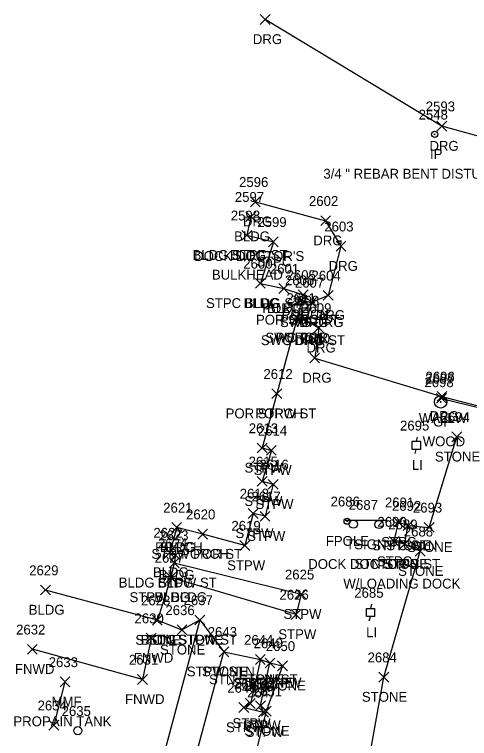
# Model space of a CAD drawing. Extents: x 1443071 to 1445292, y 614024 to 622563.
# Drawn here: x 1443947.5 to 1444039.9, y 620180.3 to 620327.3 of the extents above; entities that cross this region are included whole.
import ezdxf

# ---------------------------------------------------------------- set-up
doc = ezdxf.new("R2010")
doc.units = 0
for name, color, linetype in [('L_A', 7, 'Continuous'), ('L_C', 7, 'Continuous'), ('L_I', 7, 'Continuous'), ('L_TIC', 7, 'Continuous'), ('LASF', 7, 'Continuous'), ('LBC', 7, 'Continuous'), ('LBF', 7, 'Continuous'), ('LDEFAULT', 7, 'Continuous'), ('LFNC', 7, 'Continuous'), ('LFP', 7, 'Continuous'), ('LW', 7, 'Continuous'), ('M_A', 7, 'Continuous'), ('M_C', 7, 'Continuous'), ('M_I', 7, 'Continuous'), ('MPIR', 7, 'Continuous'), ('R_A', 7, 'Continuous'), ('R_C', 7, 'Continuous'), ('R_I', 7, 'Continuous'), ('R_TIC', 7, 'Continuous'), ('RDG', 7, 'Continuous'), ('RGP', 7, 'Continuous'), ('RSW', 7, 'Continuous'), ('S_A', 7, 'Continuous'), ('S_C', 7, 'Continuous'), ('S_I', 7, 'Continuous'), ('SSGN', 7, 'Continuous'), ('U_A', 7, 'Continuous'), ('U_I', 7, 'Continuous'), ('ULP', 7, 'Continuous'), ('UUMH', 7, 'Continuous')]:
    doc.layers.add(name, color=color, linetype=linetype)

msp = doc.modelspace()

# ---------------------------------------------------------------- linework, layer by layer
at = {"layer": 'L_TIC'}
for points in [[(1443994.5, 620285.22), (1443996.5, 620287.22)], [(1443996.5, 620285.22), (1443994.5, 620287.22)], [(1443993.68, 620281.44), (1443995.68, 620283.44)], [(1443995.68, 620281.44), (1443993.68, 620283.44)], [(1443993.68, 620281.44), (1443995.68, 620283.44)], [(1443995.68, 620281.44), (1443993.68, 620283.44)], [(1443999.07, 620280.11), (1444001.07, 620282.11)], [(1444001.07, 620280.11), (1443999.07, 620282.11)], [(1443996.43, 620271.67), (1443998.43, 620273.67)], [(1443998.43, 620271.67), (1443996.43, 620273.67)], [(1443996.43, 620271.67), (1443998.43, 620273.67)], [(1443998.43, 620271.67), (1443996.43, 620273.67)], [(1444001.18, 620270.64), (1444003.18, 620272.64)], [(1444003.18, 620270.64), (1444001.18, 620272.64)], [(1444001.18, 620270.64), (1444003.18, 620272.64)], [(1444003.18, 620270.64), (1444001.18, 620272.64)], [(1444005.13, 620269.35), (1444007.13, 620271.35)], [(1444007.13, 620269.35), (1444005.13, 620271.35)], [(1444004.85, 620268.3), (1444006.85, 620270.3)], [(1444006.85, 620268.3), (1444004.85, 620270.3)], [(1444003.9, 620264.67), (1444005.9, 620266.67)], [(1444005.9, 620264.67), (1444003.9, 620266.67)], [(1443999.79, 620249.28), (1444001.79, 620251.28)], [(1444001.79, 620249.28), (1443999.79, 620251.28)], [(1443999.79, 620249.28), (1444001.79, 620251.28)], [(1444001.79, 620249.28), (1443999.79, 620251.28)], [(1444033.21, 620248.34), (1444035.21, 620250.34)], [(1444035.21, 620248.34), (1444033.21, 620250.34)], [(1444036.34, 620240.52), (1444038.34, 620242.52)], [(1444038.34, 620240.52), (1444036.34, 620242.52)], [(1443996.81, 620238.26), (1443998.81, 620240.26)], [(1443998.81, 620238.26), (1443996.81, 620240.26)], [(1443998.66, 620237.78), (1444000.66, 620239.78)], [(1444000.66, 620237.78), (1443998.66, 620239.78)], [(1443996.78, 620231.5), (1443998.78, 620233.5)], [(1443998.78, 620231.5), (1443996.78, 620233.5)], [(1443999.04, 620230.89), (1444001.04, 620232.89)], [(1444001.04, 620230.89), (1443999.04, 620232.89)], [(1443994.97, 620224.98), (1443996.97, 620226.98)], [(1443996.97, 620224.98), (1443994.97, 620226.98)], [(1443997.37, 620224.4), (1443999.37, 620226.4)], [(1443999.37, 620224.4), (1443997.37, 620226.4)], [(1443979.43, 620222.14), (1443981.43, 620224.14)], [(1443981.43, 620222.14), (1443979.43, 620224.14)], [(1443979.43, 620222.14), (1443981.43, 620224.14)], [(1443981.43, 620222.14), (1443979.43, 620224.14)], [(1444024.47, 620223.2), (1444026.47, 620225.2)], [(1444026.47, 620223.2), (1444024.47, 620225.2)], [(1444026.45, 620222.51), (1444028.45, 620224.51)], [(1444028.45, 620222.51), (1444026.45, 620224.51)], [(1444026.45, 620222.51), (1444028.45, 620224.51)], [(1444028.45, 620222.51), (1444026.45, 620224.51)], [(1444030.72, 620222.15), (1444032.72, 620224.15)], [(1444032.72, 620222.15), (1444030.72, 620224.15)], [(1443984.72, 620220.77), (1443986.72, 620222.77)], [(1443986.72, 620220.77), (1443984.72, 620222.77)], [(1443984.72, 620220.77), (1443986.72, 620222.77)], [(1443986.72, 620220.77), (1443984.72, 620222.77)], [(1444023.61, 620219.27), (1444025.61, 620221.27)], [(1444025.61, 620219.27), (1444023.61, 620221.27)], [(1443993.28, 620218.46), (1443995.28, 620220.46)], [(1443995.28, 620218.46), (1443993.28, 620220.46)], [(1444025.72, 620218.74), (1444027.72, 620220.74)], [(1444027.72, 620218.74), (1444025.72, 620220.74)], [(1444025.72, 620218.74), (1444027.72, 620220.74)], [(1444027.72, 620218.74), (1444025.72, 620220.74)], [(1443978.01, 620217.04), (1443980.01, 620219.04)], [(1443980.01, 620217.04), (1443978.01, 620219.04)], [(1443979.19, 620216.52), (1443981.19, 620218.52)], [(1443981.19, 620216.52), (1443979.19, 620218.52)], [(1444028.87, 620217.3), (1444030.87, 620219.3)], [(1444030.87, 620217.3), (1444028.87, 620219.3)], [(1443978.95, 620214.94), (1443980.95, 620216.94)], [(1443980.95, 620214.94), (1443978.95, 620216.94)], [(1443978.95, 620214.94), (1443980.95, 620216.94)], [(1443980.95, 620214.94), (1443978.95, 620216.94)], [(1443978.26, 620211.98), (1443980.26, 620213.98)], [(1443980.26, 620211.98), (1443978.26, 620213.98)], [(1443978.26, 620211.98), (1443980.26, 620213.98)], [(1443980.26, 620211.98), (1443978.26, 620213.98)], [(1443952.79, 620209.43), (1443954.79, 620211.43)], [(1443954.79, 620209.43), (1443952.79, 620211.43)], [(1444004.73, 620208.57), (1444006.73, 620210.57)], [(1444006.73, 620208.57), (1444004.73, 620210.57)], [(1444003.68, 620204.47), (1444005.68, 620206.47)], [(1444005.68, 620204.47), (1444003.68, 620206.47)], [(1443975.5, 620203.31), (1443977.5, 620205.31)], [(1443977.5, 620203.31), (1443975.5, 620205.31)], [(1443975.5, 620203.31), (1443977.5, 620205.31)], [(1443977.5, 620203.31), (1443975.5, 620205.31)], [(1443984.13, 620203.36), (1443986.13, 620205.36)], [(1443986.13, 620203.36), (1443984.13, 620205.36)], [(1443984.13, 620203.36), (1443986.13, 620205.36)], [(1443986.13, 620203.36), (1443984.13, 620205.36)], [(1443980.5, 620201.34), (1443982.5, 620203.34)], [(1443982.5, 620201.34), (1443980.5, 620203.34)], [(1443974.25, 620199.68), (1443976.25, 620201.68)], [(1443976.25, 620199.68), (1443974.25, 620201.68)], [(1443950.11, 620197.4), (1443952.11, 620199.4)], [(1443952.11, 620197.4), (1443950.11, 620199.4)], [(1443989.03, 620196.9), (1443991.03, 620198.9)], [(1443991.03, 620196.9), (1443989.03, 620198.9)], [(1443989.03, 620196.9), (1443991.03, 620198.9)], [(1443991.03, 620196.9), (1443989.03, 620198.9)], [(1443996.43, 620195.31), (1443998.43, 620197.31)], [(1443998.43, 620195.31), (1443996.43, 620197.31)], [(1443996.43, 620195.31), (1443998.43, 620197.31)], [(1443998.43, 620195.31), (1443996.43, 620197.31)], [(1443998.37, 620194.62), (1444000.37, 620196.62)], [(1444000.37, 620194.62), (1443998.37, 620196.62)], [(1443998.37, 620194.62), (1444000.37, 620196.62)], [(1444000.37, 620194.62), (1443998.37, 620196.62)], [(1444000.92, 620194.04), (1444002.92, 620196.04)], [(1444002.92, 620194.04), (1444000.92, 620196.04)], [(1443972.47, 620191.28), (1443974.47, 620193.28)], [(1443974.47, 620191.28), (1443972.47, 620193.28)], [(1444021.51, 620191.75), (1444023.51, 620193.75)], [(1444023.51, 620191.75), (1444021.51, 620193.75)], [(1443956.73, 620190.78), (1443958.73, 620192.78)], [(1443958.73, 620190.78), (1443956.73, 620192.78)], [(1443993.06, 620185.58), (1443995.06, 620187.58)], [(1443995.06, 620185.58), (1443993.06, 620187.58)], [(1443994.39, 620186.41), (1443996.39, 620188.41)], [(1443996.39, 620186.41), (1443994.39, 620188.41)], [(1443996.45, 620185.96), (1443998.45, 620187.96)], [(1443998.45, 620185.96), (1443996.45, 620187.96)], [(1443997.05, 620184.62), (1443999.05, 620186.62)], [(1443999.05, 620184.62), (1443997.05, 620186.62)], [(1443997.63, 620184.84), (1443999.63, 620186.84)], [(1443999.63, 620184.84), (1443997.63, 620186.84)], [(1443954.48, 620181.99), (1443956.48, 620183.99)], [(1443956.48, 620181.99), (1443954.48, 620183.99)]]:
    msp.add_lwpolyline(points, dxfattribs=at)
at = {"layer": 'LASF'}
msp.add_lwpolyline([(1443976.5, 620204.31), (1443981.5, 620202.34), (1443985.13, 620204.36), (1443990.03, 620197.9), (1443997.43, 620196.31), (1443999.37, 620195.62), (1444001.92, 620195.04), (1443998.63, 620185.84), (1443991.95, 620159.42), (1443988.85, 620147.15), (1443986.19, 620136.52), (1443986.57, 620129.75), (1444004.87, 620124.73), (1444012.6, 620137.5), (1444022.51, 620192.75), (1444029.87, 620218.3), (1444026.72, 620219.74), (1444027.45, 620223.51), (1444031.72, 620223.15), (1444037.34, 620241.52)], dxfattribs=at)
at = {"layer": 'LBC'}
for points in [[(1443995.5, 620286.22), (1443994.68, 620282.44)], [(1443997.43, 620272.67), (1444002.18, 620271.64)], [(1443980.43, 620223.14), (1443979.01, 620218.04), (1443980.19, 620217.52), (1443979.95, 620215.94), (1443979.26, 620212.98), (1443976.5, 620204.31), (1443953.79, 620210.43)]]:
    msp.add_lwpolyline(points, dxfattribs=at)
at = {"layer": 'LBF'}
for points in [[(1443994.68, 620282.44), (1444000.07, 620281.11), (1443997.43, 620272.67)], [(1444002.18, 620271.64), (1444006.13, 620270.35), (1444005.85, 620269.3), (1444004.9, 620265.67), (1444000.79, 620250.28)], [(1444000.79, 620250.28), (1443997.81, 620239.26), (1443999.66, 620238.78), (1443997.78, 620232.5), (1444000.04, 620231.89), (1443998.37, 620225.4), (1443995.97, 620225.98), (1443994.28, 620219.46), (1443985.72, 620221.77)], [(1444026.72, 620219.74), (1444024.61, 620220.27), (1444025.47, 620224.2), (1444027.45, 620223.51)], [(1443985.72, 620221.77), (1443980.43, 620223.14)], [(1443979.95, 620215.94), (1444005.73, 620209.57), (1444004.68, 620205.47), (1443979.26, 620212.98)], [(1443985.13, 620204.36), (1443975.11, 620166.96), (1443990.62, 620162.19), (1443992.36, 620167.94), (1443985.21, 620169.98), (1443983.8, 620174.72), (1443990.03, 620197.9)], [(1443997.43, 620196.31), (1443995.39, 620187.41), (1443994.06, 620186.58), (1443998.05, 620185.62), (1443997.45, 620186.96), (1443999.37, 620195.62)]]:
    msp.add_lwpolyline(points, dxfattribs=at)
at = {"layer": 'LDEFAULT'}
msp.add_lwpolyline([(1443957.73, 620191.78), (1443955.48, 620182.99)], dxfattribs=at)
at = {"layer": 'LFNC'}
msp.add_lwpolyline([(1443975.25, 620200.68), (1443973.47, 620192.28), (1443951.11, 620198.4)], dxfattribs=at)
at = {"layer": 'LFP'}
for radius in [0.625, 0.0833]:
    msp.add_circle((1444015.05, 620224.39), radius, dxfattribs=at)
at = {"layer": 'LW'}
msp.add_lwpolyline([(1444034.21, 620249.34), (1444044.78, 620246.72), (1444050.66, 620270.57), (1444050.35, 620270.75)], dxfattribs=at)
at = {"layer": 'MPIR'}
for radius in [0.625, 0.0833]:
    msp.add_circle((1444032.83, 620302.93), radius, dxfattribs=at)
at = {"layer": 'R_TIC'}
for points in [[(1443997.41, 620325.25), (1443999.41, 620327.25)], [(1443999.41, 620325.25), (1443997.41, 620327.25)], [(1444033.28, 620303.59), (1444035.28, 620305.59)], [(1444035.28, 620303.59), (1444033.28, 620305.59)], [(1443995.41, 620288.24), (1443997.41, 620290.24)], [(1443997.41, 620288.24), (1443995.41, 620290.24)], [(1444009.68, 620284.39), (1444011.68, 620286.39)], [(1444011.68, 620284.39), (1444009.68, 620286.39)], [(1444012.79, 620279.22), (1444014.79, 620281.22)], [(1444014.79, 620279.22), (1444012.79, 620281.22)], [(1444010.2, 620269.24), (1444012.2, 620271.24)], [(1444012.2, 620269.24), (1444010.2, 620271.24)], [(1444004.85, 620268.3), (1444006.85, 620270.3)], [(1444006.85, 620268.3), (1444004.85, 620270.3)], [(1444006.82, 620267.81), (1444008.82, 620269.81)], [(1444008.82, 620267.81), (1444006.82, 620269.81)], [(1444006.82, 620267.81), (1444008.82, 620269.81)], [(1444008.82, 620267.81), (1444006.82, 620269.81)], [(1444003.9, 620264.67), (1444005.9, 620266.67)], [(1444005.9, 620264.67), (1444003.9, 620266.67)], [(1444005.82, 620264.14), (1444007.82, 620266.14)], [(1444007.82, 620264.14), (1444005.82, 620266.14)], [(1444005.82, 620264.14), (1444007.82, 620266.14)], [(1444007.82, 620264.14), (1444005.82, 620266.14)], [(1444008.31, 620262.64), (1444010.31, 620264.64)], [(1444010.31, 620262.64), (1444008.31, 620264.64)], [(1444007.46, 620256.52), (1444009.46, 620258.52)], [(1444009.46, 620256.52), (1444007.46, 620258.52)], [(1444033.32, 620248.74), (1444035.32, 620250.74)], [(1444035.32, 620248.74), (1444033.32, 620250.74)]]:
    msp.add_lwpolyline(points, dxfattribs=at)
at = {"layer": 'RDG'}
for points in [[(1444067.43, 620324.85), (1444069.07, 620313.31), (1444066.3, 620300.78), (1444063.63, 620298.79), (1444051.48, 620299.88), (1444034.28, 620304.59), (1443998.41, 620326.25)], [(1443996.41, 620289.24), (1444010.68, 620285.39), (1444013.79, 620280.22), (1444011.2, 620270.24), (1444007.82, 620268.81)], [(1444006.82, 620265.14), (1444009.31, 620263.64), (1444008.46, 620257.52), (1444034.32, 620249.74), (1444044.54, 620247.09), (1444050.35, 620270.75), (1444052.51, 620273.19), (1444063.33, 620265.17), (1444066.93, 620257.79), (1444075.53, 620245.02)]]:
    msp.add_lwpolyline(points, dxfattribs=at)
at = {"layer": 'RGP'}
msp.add_line((1444034.05, 620248.61), (1444034.05, 620248.61), dxfattribs=at)
for radius in [1.25, 0.0833]:
    msp.add_circle((1444034.05, 620248.61), radius, dxfattribs=at)
at = {"layer": 'RSW'}
msp.add_lwpolyline([(1444005.85, 620269.3), (1444007.82, 620268.81), (1444006.82, 620265.14), (1444004.9, 620265.67)], dxfattribs=at)
at = {"layer": 'SSGN'}
for p, q in [((1444014.66, 620224.63), (1444023.26, 620224.63)), ((1444018.68, 620223.73), (1444018.68, 620223.73))]:
    msp.add_line(p, q, dxfattribs=at)
for centre in [(1444016.32, 620223.8), (1444021.54, 620223.73)]:
    msp.add_circle(centre, 0.833, dxfattribs=at)
at = {"layer": 'ULP'}
for p, q in [((1444029.26, 620241.48), (1444029.1, 620240.65)), ((1444028.26, 620238.98), (1444028.26, 620240.65)), ((1444028.26, 620240.65), (1444029.93, 620240.65)), ((1444029.93, 620240.65), (1444029.93, 620238.98)), ((1444029.93, 620238.98), (1444028.26, 620238.98)), ((1444028.85, 620238.15), (1444029.1, 620238.98)), ((1444029.1, 620239.81), (1444029.1, 620239.81)), ((1444018.97, 620205.03), (1444018.97, 620206.7)), ((1444018.97, 620206.7), (1444020.64, 620206.7)), ((1444019.97, 620207.53), (1444019.8, 620206.7)), ((1444020.64, 620206.7), (1444020.64, 620205.03)), ((1444020.64, 620205.03), (1444018.97, 620205.03)), ((1444019.55, 620204.2), (1444019.8, 620205.03)), ((1444019.8, 620205.86), (1444019.8, 620205.86))]:
    msp.add_line(p, q, dxfattribs=at)
at = {"layer": 'UUMH'}
for p, q in [((1443960.36, 620181.87), (1443960.36, 620181.87)), ((1443961.2, 620181.87), (1443961.2, 620181.87))]:
    msp.add_line(p, q, dxfattribs=at)
msp.add_circle((1443960.36, 620181.87), 0.833, dxfattribs=at)

# ---------------------------------------------------------------- texts
at = {"layer": 'L_A'}
for s, p in [('BLDG', (1443992.09, 620281.22)), ('BLDG STPC ST', (1443983.65, 620277.44)), ('BLDG', (1443991.27, 620277.44)), ('STPC', (1443996.59, 620276.11)), ('STPC BLDG ST', (1443986.39, 620267.67)), ('BLDG', (1443994.02, 620267.67)), ('PORCH', (1443997.81, 620266.64)), ('BLDG', (1443998.77, 620266.64)), ('PORCH', (1444001.75, 620265.35)), ('PORCH', (1444001.47, 620264.3)), ('PORCH', (1444000.52, 620260.67)), ('POR STPW ST', (1443990.37, 620245.28)), ('PORCH', (1443996.41, 620245.28)), ('WALLW', (1444029.62, 620244.34)), ('STONE', (1444032.88, 620236.52)), ('STPW', (1443994.21, 620234.26)), ('STPW', (1443996.05, 620233.78)), ('STPW', (1443994.18, 620227.5)), ('STPW', (1443996.43, 620226.89)), ('STPW', (1443992.37, 620220.98)), ('STPW', (1443994.76, 620220.4)), ('FPOLE', (1444010.72, 620219.39)), ('STPC', (1444021.98, 620219.2)), ('PORCH', (1443976.05, 620218.14)), ('BLDG', (1443977.02, 620218.14)), ('STPC STN', (1444020.15, 620218.51)), ('STONE', (1444023, 620218.51)), ('STONE', (1444027.26, 620218.15)), ('STPW POR ST', (1443975.3, 620216.77)), ('PORCH', (1443981.34, 620216.77)), ('STPW', (1443990.68, 620214.46)), ('STN STPC ST', (1444016.56, 620214.74)), ('STPC', (1444021.12, 620215.27)), ('STONE', (1444022.27, 620214.74)), ('BLDG', (1443975.6, 620213.04)), ('STONE', (1444025.41, 620213.3)), ('BLDG', (1443976.78, 620212.52)), ('BLDG STPW ST', (1443968.66, 620210.94)), ('BLDG', (1443976.54, 620210.94)), ('STPW BLDG', (1443970.84, 620207.98)), ('BLDG', (1443975.85, 620207.98)), ('BLDG', (1443950.38, 620205.43)), ('STPW', (1444002.12, 620204.57)), ('STPW', (1444001.07, 620200.47)), ('STONE', (1443972.04, 620199.31)), ('BLDG', (1443973.09, 620199.31)), ('STN STPW ST', (1443974.71, 620199.36)), ('STONE', (1443980.67, 620199.36)), ('STONE', (1443977.04, 620197.34)), ('FNWD', (1443971.72, 620195.68)), ('FNWD', (1443947.58, 620193.4)), ('STPW STN', (1443982.48, 620192.9)), ('STONE', (1443985.58, 620192.9)), ('STN STPW ST', (1443987.01, 620191.31)), ('STONE', (1443992.98, 620191.31)), ('STN STPW', (1443991.95, 620190.62)), ('STONE', (1443994.91, 620190.62)), ('STONE', (1443997.47, 620190.04)), ('MMF', (1443955.02, 620186.78)), ('FNWD', (1443969.94, 620187.28)), ('STONE', (1444018.05, 620187.75)), ('STPW', (1443991.78, 620182.41)), ('STPW', (1443990.45, 620181.58)), ('STPW', (1443993.84, 620181.96)), ('STONE', (1443994.17, 620180.84)), ('STPW', (1443994.44, 620180.62))]:
    msp.add_text(s, height=2, dxfattribs=at).set_placement(p)
at = {"layer": 'L_C'}
for s, p in [("DOCK DOCTOR'S", (1443983.98, 620277.22)), ('BULKHEAD', (1443987.58, 620273.44)), ('W/LOADING DOCK', (1444014.28, 620210.74)), ('PROPAIN TANK', (1443947.26, 620182.78))]:
    msp.add_text(s, height=2, dxfattribs=at).set_placement(p)
at = {"layer": 'L_I'}
for s, p in [('2597', (1443992.24, 620289.22)), ('2598', (1443991.42, 620285.44)), ('2598', (1443991.42, 620285.44)), ('2599', (1443996.81, 620284.11)), ('2600', (1443993.95, 620275.67)), ('2600', (1443993.95, 620275.67)), ('2601', (1443999.36, 620274.64)), ('2601', (1443999.36, 620274.64)), ('2605', (1444002.74, 620273.35)), ('2606', (1444002.41, 620272.3)), ('2611', (1444002.72, 620268.67)), ('2612', (1443998.05, 620253.28)), ('2612', (1443998.05, 620253.28)), ('2697', (1444030.9, 620252.34)), ('2694', (1444034.03, 620244.52)), ('2613', (1443995.07, 620242.26)), ('2614', (1443996.92, 620241.78)), ('2615', (1443995.04, 620235.5)), ('2616', (1443997.24, 620234.89)), ('2618', (1443993.23, 620228.98)), ('2617', (1443995.63, 620228.4)), ('2686', (1444011.69, 620227.39)), ('2691', (1444022.73, 620227.2)), ('2692', (1444024.14, 620226.51)), ('2692', (1444024.14, 620226.51)), ('2621', (1443977.69, 620226.14)), ('2621', (1443977.69, 620226.14)), ('2620', (1443982.33, 620224.77)), ('2620', (1443982.33, 620224.77)), ('2693', (1444028.41, 620226.15)), ('2690', (1444021.21, 620223.27)), ('2619', (1443991.54, 620222.46)), ('2689', (1444023.41, 620222.74)), ('2689', (1444023.41, 620222.74)), ('2622', (1443975.7, 620221.04)), ('2623', (1443976.88, 620220.52)), ('2688', (1444026.56, 620221.3)), ('2624', (1443976.64, 620218.94)), ('2624', (1443976.64, 620218.94)), ('2627', (1443975.95, 620215.98)), ('2627', (1443975.95, 620215.98)), ('2629', (1443950.47, 620213.43)), ('2625', (1444002.42, 620212.57)), ('2628', (1443973.19, 620207.31)), ('2628', (1443973.19, 620207.31)), ('2637', (1443981.82, 620207.36)), ('2637', (1443981.82, 620207.36)), ('2626', (1444001.31, 620208.47)), ('2636', (1443978.14, 620205.34)), ('2630', (1443971.86, 620203.68)), ('2632', (1443947.81, 620201.4)), ('2643', (1443986.73, 620200.9)), ('2643', (1443986.73, 620200.9)), ('2644', (1443994.12, 620199.31)), ('2644', (1443994.12, 620199.31)), ('2649', (1443996.05, 620198.62)), ('2649', (1443996.05, 620198.62)), ('2650', (1443998.53, 620198.04)), ('2684', (1444019.2, 620195.75)), ('2633', (1443954.43, 620194.78)), ('2631', (1443970.73, 620195.28)), ('2646', (1443990.7, 620189.58)), ('2645', (1443992.08, 620190.41)), ('2648', (1443994.14, 620189.96)), ('2647', (1443994.74, 620188.62)), ('2651', (1443995.89, 620188.84)), ('2634', (1443952.17, 620185.99))]:
    msp.add_text(s, height=2, dxfattribs=at).set_placement(p)
at = {"layer": 'M_A'}
msp.add_text('IP', height=2, dxfattribs=at).set_placement((1444031.88, 620297.93))
at = {"layer": 'M_C'}
msp.add_text('3/4 " REBAR BENT DISTURBED', height=2, dxfattribs=at).set_placement((1444010.23, 620293.93))
at = {"layer": 'M_I'}
msp.add_text('2548', height=2, dxfattribs=at).set_placement((1444029.57, 620305.93))
at = {"layer": 'R_A'}
for s, p in [('DRG', (1443995.9, 620321.25)), ('DRG', (1444031.77, 620299.59)), ('DRG', (1443993.9, 620284.24)), ('DRG', (1444008.17, 620280.39)), ('DRG', (1444011.28, 620275.22)), ('DRG', (1444008.69, 620265.24)), ('POR SWC ST', (1443996.54, 620264.3)), ('SWC DRG', (1444001.4, 620263.81)), ('DRG', (1444005.31, 620263.81)), ('SWC DRG ST', (1443997.53, 620260.14)), ('SWC POR', (1443998.45, 620260.67)), ('DRG', (1444004.3, 620260.14)), ('DRG', (1444006.79, 620258.64)), ('DRG', (1444005.94, 620252.52)), ('DRG', (1444031.81, 620244.74)), ('GP', (1444032.49, 620243.61))]:
    msp.add_text(s, height=2, dxfattribs=at).set_placement(p)
at = {"layer": 'R_C'}
msp.add_text('WOOD', height=2, dxfattribs=at).set_placement((1444030.41, 620239.61))
at = {"layer": 'R_I'}
for s, p in [('2593', (1444031.02, 620307.59)), ('2596', (1443993.1, 620292.24)), ('2602', (1444007.3, 620288.39)), ('2603', (1444010.41, 620283.22)), ('2604', (1444007.81, 620273.24)), ('2606', (1444002.41, 620272.3)), ('2607', (1444004.43, 620271.81)), ('2607', (1444004.43, 620271.81)), ('2611', (1444002.72, 620268.67)), ('2608', (1444003.43, 620268.14)), ('2608', (1444003.43, 620268.14)), ('2609', (1444005.91, 620266.64)), ('2610', (1444005.63, 620260.52)), ('2696', (1444030.96, 620252.74)), ('2698', (1444030.75, 620251.61))]:
    msp.add_text(s, height=2, dxfattribs=at).set_placement(p)
at = {"layer": 'S_A'}
msp.add_text('TSIGN', height=2, dxfattribs=at).set_placement((1444014.86, 620218.71))
at = {"layer": 'S_C'}
msp.add_text("DOCK DOCTOR'S", height=2, dxfattribs=at).set_placement((1444007.15, 620214.71))
at = {"layer": 'S_I'}
msp.add_text('2687', height=2, dxfattribs=at).set_placement((1444015.37, 620226.71))
at = {"layer": 'U_A'}
for p in [(1444028.2, 620234.81), (1444018.91, 620200.86)]:
    msp.add_text('LI', height=2, dxfattribs=at).set_placement(p)
at = {"layer": 'U_I'}
for s, p in [('2695', (1444025.79, 620242.81)), ('2685', (1444016.5, 620208.86)), ('2635', (1443957.06, 620184.87))]:
    msp.add_text(s, height=2, dxfattribs=at).set_placement(p)

doc.saveas('drawing.dxf')
